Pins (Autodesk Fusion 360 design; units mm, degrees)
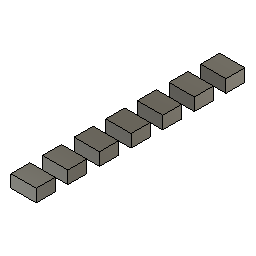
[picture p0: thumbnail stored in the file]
parameter "Hight_Z" = 1
sketch "Sketch1" plane through (0, 0, 0) normal (0, 0, 1) x axis (1, 0, 0)
  line L1 (-2, 0) -> (0, 0)
  line L2 (-2, 1.5) -> (-2, 0)
  line L3 (0, 1.5) -> (-2, 1.5)
  line L4 (0, 0) -> (0, 1.5)
  point P1 (0, 0)
  point P2 (0, 0)
  point P3 (-2, 0)
  point P4 (-2, 1.5)
  horizontal L1
  vertical L2
  horizontal L3
  vertical L4
  coincident P1 P2
  dimension "d2" distance P3 P4 = 1.5 (= "( 1.5 * Ratio ) * 1 mm")
  dimension "d3" distance P2 P3 = 2 (= "( 2 * Ratio ) * 1 mm")
extrude "Extrude1" new body sketch "Sketch1" along normal blind 1 (= "Hight_Z")
rectangular_pattern "R-Pattern1" uSpaceDistance 15 (= "15 mm * Ratio") vSpaceDistance 0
